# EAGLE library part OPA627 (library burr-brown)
Difet(R) Operational Amplifiers Precision, High-Speed
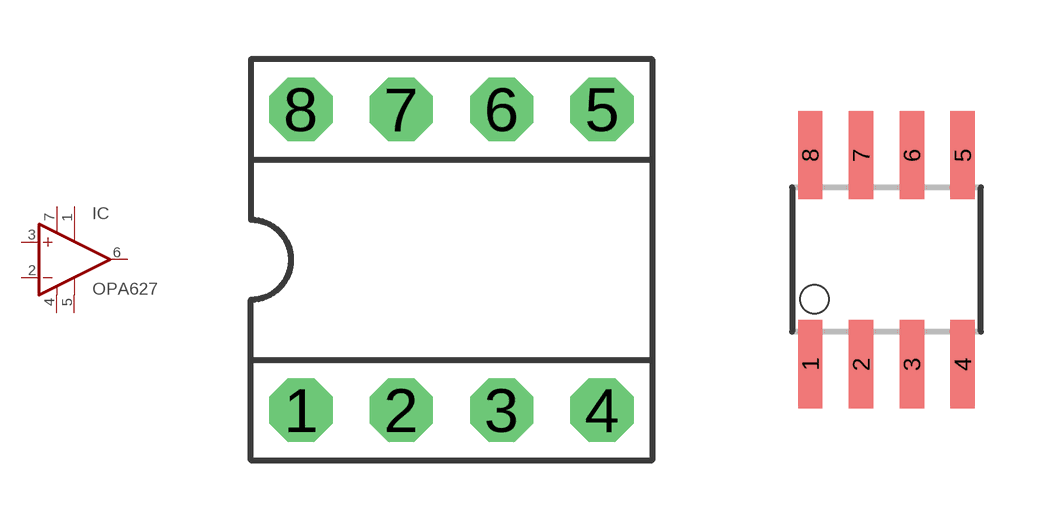
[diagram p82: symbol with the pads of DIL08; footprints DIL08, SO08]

Designator prefix IC

## OPA627P (MF: TEXAS INSTRUMENTS; MPN: OPA627BP; OC_FARNELL: 1212318; OC_NEWARK: 35C1918)  [DIL08]
1  TRIM1  pas
2  -IN  in
3  +IN  in
4  V-  pwr
5  TRIM2  pas
6  OUT  out
7  V+  pwr

## OPA627U (MF: TEXAS INSTRUMENTS; MPN: OPA627AU; OC_FARNELL: 1207067; OC_NEWARK: 30C4516)  [SO08]
Pads as for DIL08

## Footprint DIL08 (pad centres in mm)
Dual In Line
drill 0.813 pad 1.6 octagon: 1 -3.81,-3.81; 2 -1.27,-3.81; 3 1.27,-3.81; 4 3.81,-3.81; 5 3.81,3.81; 6 1.27,3.81; 7 -1.27,3.81; 8 -3.81,3.81

## Footprint SO08 (pad centres in mm)
Small Outline Package
smd 0.61 x 2.21: 1 -1.905,-2.616; 2 -0.635,-2.616; 3 0.635,-2.616; 4 1.905,-2.616; 5 1.905,2.616; 6 0.635,2.616; 7 -0.635,2.616; 8 -1.905,2.616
